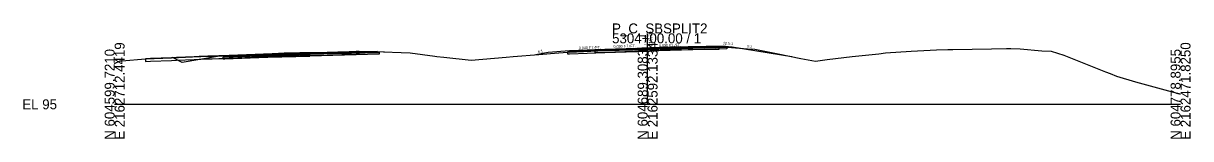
# Model space of a CAD drawing. Extents: x -26 to 1303, y -10 to 12033.
# Drawn here: x 974.3 to 1302.8, y -9.7 to 22.8 of the extents above; entities that cross this region are included whole.
import ezdxf

# ---------------------------------------------------------------- set-up
doc = ezdxf.new("R2010")
doc.units = 0
for name, color, linetype in [('RD_GPK_XS_Cell', 7, 'Continuous'), ('RD_XS_Base', 7, 'Continuous'), ('RD_XS_ExGround', 7, 'Continuous'), ('RD_XS_ExPaveRet', 7, 'Continuous'), ('RD_XS_Greenside', 7, 'Continuous'), ('RD_XS_Pave', 7, 'Continuous'), ('RD_XS_PaveOvlay_CP', 7, 'Continuous'), ('RD_XS_TieSlope', 7, 'Continuous'), ('RD_XS_TX_Elev_EX', 7, 'Continuous'), ('RD_XS_TX_Elev_PR', 7, 'Continuous'), ('RD_XS_TX_ShdSlope', 7, 'Continuous'), ('RD_XS_TX_Slope', 7, 'Continuous')]:
    doc.layers.add(name, color=color, linetype=linetype)

msp = doc.modelspace()

# ---------------------------------------------------------------- linework, layer by layer
at = {"layer": 'RD_GPK_XS_Cell'}
for p, q in [((1150, 0), (1150, 20)), ((1000, 0), (1150, 0)), ((1150, 0), (1300, 0))]:
    msp.add_line(p, q, dxfattribs=at)
at = {"layer": 'RD_XS_Base'}
for p, q in [((1030.97, 13.33), (1030.47, 13.31)), ((1030.47, 13.31), (1030.47, 13.31)), ((1030.47, 13.31), (1030.47, 12.81)), ((1031.04, 13.33), (1030.97, 13.33)), ((1042.97, 13.81), (1031.04, 13.33)), ((1031.04, 12.83), (1042.97, 13.31)), ((1043.1, 13.81), (1042.97, 13.81)), ((1042.97, 13.31), (1043.1, 13.31)), ((1054.97, 14.12), (1043.1, 13.81)), ((1043.1, 13.31), (1054.97, 13.62)), ((1054.97, 14.12), (1074.47, 14.62)), ((1054.97, 13.62), (1054.97, 14.28)), ((1054.97, 14.28), (1054.97, 14.28)), ((1054.97, 14.28), (1054.97, 14.28)), ((1054.97, 14.28), (1054.97, 14.12)), ((1074.47, 14.12), (1054.97, 13.62)), ((1054.97, 14.12), (1054.97, 14.12)), ((1054.97, 13.62), (1054.97, 14.12)), ((1054.97, 14.12), (1054.97, 14.12)), ((1054.97, 14.12), (1054.97, 14.12)), ((1054.97, 13.62), (1054.97, 13.62)), ((1073.97, 14.61), (1073.97, 14.61)), ((1074.47, 14.62), (1074.47, 14.12)), ((1074.47, 14.59), (1074.47, 14.59)), ((1128, 14.74), (1127.5, 14.72)), ((1127.5, 14.72), (1127.5, 14.72)), ((1127.5, 14.72), (1127.5, 14.22)), ((1127.5, 14.22), (1128, 14.24)), ((1138, 15.14), (1128, 14.74)), ((1128, 14.74), (1128, 14.74)), ((1128, 14.24), (1138, 14.64)), ((1128, 14.24), (1128, 14.24)), ((1150, 15.47), (1138, 15.14)), ((1138, 15.14), (1138, 15.14)), ((1138, 14.64), (1150, 14.97)), ((1138, 14.64), (1138, 14.64)), ((1150, 15.47), (1171.79, 16.08)), ((1150, 14.97), (1150, 15.63)), ((1150, 15.63), (1150, 15.63)), ((1150, 15.63), (1150, 15.63)), ((1150, 15.63), (1150, 15.47)), ((1172.29, 15.6), (1150, 14.97)), ((1150, 15.47), (1150, 15.47)), ((1150, 14.97), (1150, 15.47)), ((1150, 15.47), (1150, 15.47)), ((1150, 15.47), (1150, 15.47)), ((1150, 14.97), (1150, 14.97)), ((1162, 15.81), (1162, 15.81)), ((1162, 15.81), (1162, 15.81)), ((1162, 15.31), (1162, 15.31)), ((1162, 15.31), (1162, 15.31)), ((1171.79, 16.08), (1171.79, 16.08)), ((1172.29, 16.1), (1172.29, 15.6)), ((1172.29, 16.06), (1172.29, 16.06)), ((1030.47, 12.81), (1030.97, 12.83)), ((1030.47, 12.81), (1030.47, 12.81)), ((1030.47, 12.81), (1030.47, 12.81)), ((1030.97, 12.83), (1031.04, 12.83))]:
    msp.add_line(p, q, dxfattribs=at)
at = {"layer": 'RD_XS_ExGround'}
msp.add_lwpolyline([(1000, 11.48), (1001.53, 12.23), (1001.99, 12.23), (1008.73, 12.85), (1015.97, 13.15), (1023.91, 13.48), (1024.23, 13.5), (1024.28, 13.5), (1028.18, 13.59), (1030.24, 13.67), (1034.66, 13.85), (1046.14, 14.36), (1049.24, 14.41), (1051.95, 14.46), (1053.23, 14.53), (1053.31, 14.53), (1054.68, 14.5), (1054.89, 14.5), (1064.52, 14.77), (1068.78, 14.9), (1071.33, 14.89), (1075.69, 14.78), (1080.66, 14.64), (1083.18, 14.53), (1090.16, 13.58), (1090.71, 13.5), (1092.65, 13.29), (1100.38, 12.45), (1110.16, 13.34), (1112.17, 13.5), (1119.36, 14.06), (1124.88, 14.5), (1124.99, 14.5), (1135.02, 15.3), (1135.19, 15.32), (1135.28, 15.32), (1146.34, 15.69), (1148.42, 15.79), (1150.59, 15.9), (1156.31, 16.11), (1166.5, 16.28), (1170.15, 16.28), (1172.5, 16.08), (1178.1, 15.67), (1180.14, 15.51), (1183, 15), (1186.73, 14.25), (1193.13, 12.91), (1197.3, 12.18), (1200.58, 12.6), (1207.59, 13.5), (1215.08, 14.28), (1216.98, 14.49), (1224.18, 14.94), (1231.33, 15.38), (1234.46, 15.46), (1234.73, 15.47), (1235.93, 15.49), (1246.83, 15.69), (1251.05, 15.75), (1252.26, 15.73), (1254.86, 15.67), (1260.98, 15.11), (1263.56, 14.96), (1267.1, 13.83), (1278.92, 9.17), (1280.16, 8.65), (1281.97, 7.97), (1287.32, 6.32), (1297.62, 3.56), (1300, 2.93)], dxfattribs=at)
at = {"layer": 'RD_XS_ExPaveRet'}
for points in [[(1068.78, 14.9), (1068.78, 14.9), (1068.54, 14.9), (1067.96, 14.88), (1063.93, 14.75), (1062.81, 14.73), (1056.82, 14.56), (1055.02, 14.52), (1054.15, 14.51), (1053.39, 14.53), (1053.32, 14.53), (1053.23, 14.53), (1053.2, 14.53), (1053.19, 14.53), (1052.4, 14.49), (1052.1, 14.47), (1051.6, 14.46), (1047.74, 14.39), (1046.74, 14.37), (1046.14, 14.36), (1044.37, 14.28), (1034.66, 13.85), (1032.19, 13.75), (1030.24, 13.67), (1029.34, 13.64), (1027.42, 13.59), (1026.26, 13.54), (1024.23, 13.48), (1023.94, 13.48), (1023.76, 13.48), (1022.39, 13.42), (1017.39, 13.21), (1015.97, 13.15), (1010.05, 12.9), (1008.73, 12.85), (1008.73, 12.85), (1008.73, 12.85), (1008.73, 12.63), (1008.73, 12.1), (1008.73, 12.1), (1008.73, 12.1), (1010.05, 12.15), (1015.97, 12.4), (1017.39, 12.46), (1022.39, 12.67), (1023.76, 12.73), (1023.94, 12.73), (1024.23, 12.73), (1026.26, 12.79), (1027.42, 12.84), (1029.34, 12.89), (1030.24, 12.92), (1032.19, 13), (1034.66, 13.1), (1044.37, 13.53), (1046.14, 13.61), (1046.74, 13.62), (1047.74, 13.64), (1051.6, 13.71), (1052.1, 13.72), (1052.4, 13.74), (1053.19, 13.78), (1053.2, 13.78), (1053.23, 13.78), (1053.32, 13.78), (1053.39, 13.78), (1054.15, 13.76), (1055.02, 13.77), (1056.82, 13.81), (1062.81, 13.98), (1063.93, 14), (1067.96, 14.13), (1068.54, 14.15), (1068.78, 14.15), (1068.78, 14.15), (1068.78, 14.15), (1068.78, 14.72), (1068.78, 14.9), (1068.78, 14.9)], [(1068.78, 14.9), (1068.78, 14.9), (1068.54, 14.9), (1067.96, 14.88), (1063.93, 14.75), (1062.81, 14.73), (1056.82, 14.56), (1055.02, 14.52), (1054.15, 14.51), (1053.39, 14.53), (1053.32, 14.53), (1053.23, 14.53), (1053.2, 14.53), (1053.19, 14.53), (1052.4, 14.49), (1052.1, 14.47), (1051.6, 14.46), (1047.74, 14.39), (1046.74, 14.37), (1046.14, 14.36), (1044.37, 14.28), (1034.66, 13.85), (1032.19, 13.75), (1030.24, 13.67), (1029.34, 13.64), (1027.42, 13.59), (1026.26, 13.54), (1024.23, 13.48), (1023.94, 13.48), (1023.76, 13.48), (1022.39, 13.42), (1017.39, 13.21), (1015.97, 13.15), (1010.05, 12.9), (1008.73, 12.85), (1008.73, 12.63), (1008.73, 12.1), (1010.05, 12.15), (1015.97, 12.4), (1017.39, 12.46), (1022.39, 12.67), (1023.76, 12.73), (1023.94, 12.73), (1024.23, 12.73), (1026.26, 12.79), (1027.42, 12.84), (1029.34, 12.89), (1030.24, 12.92), (1032.19, 13), (1034.66, 13.1), (1044.37, 13.53), (1046.14, 13.61), (1046.74, 13.62), (1047.74, 13.64), (1051.6, 13.71), (1052.1, 13.72), (1052.4, 13.74), (1053.19, 13.78), (1053.2, 13.78), (1053.23, 13.78), (1053.32, 13.78), (1053.39, 13.78), (1054.15, 13.76), (1055.02, 13.77), (1056.82, 13.81), (1062.81, 13.98), (1063.93, 14), (1067.96, 14.13), (1068.54, 14.15), (1068.78, 14.15), (1068.78, 14.15), (1068.78, 14.72), (1068.78, 14.9)], [(1166.5, 16.28), (1156.31, 16.11), (1156.31, 16.11), (1156.31, 16.11), (1150.59, 15.9), (1148.42, 15.79), (1148.42, 15.79), (1146.34, 15.69), (1146.34, 15.69), (1146.34, 15.69), (1135.28, 15.32), (1135.28, 15.32), (1135.19, 15.32), (1135.19, 15.32), (1135.19, 14.57), (1135.28, 14.57), (1135.28, 14.57), (1146.34, 14.94), (1146.34, 14.94), (1146.34, 14.94), (1148.42, 15.04), (1148.42, 15.04), (1150.59, 15.15), (1156.31, 15.36), (1156.31, 15.36), (1156.31, 15.36), (1166.5, 15.53), (1166.5, 15.53), (1170.15, 15.53), (1170.15, 16.28), (1170.15, 16.28), (1166.5, 16.28), (1166.5, 16.28)], [(1166.5, 16.28), (1156.31, 16.11), (1150.59, 15.9), (1148.42, 15.79), (1146.34, 15.69), (1135.28, 15.32), (1135.19, 15.32), (1135.19, 14.57), (1135.28, 14.57), (1146.34, 14.94), (1148.42, 15.04), (1150.59, 15.15), (1156.31, 15.36), (1166.5, 15.53), (1170.15, 15.53), (1170.15, 16.28), (1166.5, 16.28)]]:
    msp.add_lwpolyline(points, dxfattribs=at)
at = {"layer": 'RD_XS_Greenside'}
for p, q in [((1018.97, 11.82), (1016.27, 13.17)), ((1028.97, 13.48), (1018.97, 11.82)), ((1122, 14.58), (1118.52, 13.99)), ((1173.79, 16.24), (1190.59, 13.44))]:
    msp.add_line(p, q, dxfattribs=at)
at = {"layer": 'RD_XS_Pave'}
for p, q in [((1031.04, 13.65), (1030.97, 13.64)), ((1030.97, 13.64), (1030.97, 13.49)), ((1030.97, 13.49), (1030.97, 13.48)), ((1030.97, 13.48), (1031.04, 13.49)), ((1031.04, 13.49), (1030.97, 13.48)), ((1030.97, 13.48), (1030.97, 13.33)), ((1030.97, 13.33), (1030.97, 13.33)), ((1030.97, 13.33), (1031.04, 13.33)), ((1042.97, 14.12), (1031.04, 13.65)), ((1031.04, 13.49), (1042.97, 13.96)), ((1042.97, 13.96), (1031.04, 13.49)), ((1031.04, 13.33), (1042.97, 13.81)), ((1043.1, 14.13), (1042.97, 14.12)), ((1042.97, 13.96), (1043.1, 13.97)), ((1043.1, 13.97), (1042.97, 13.96)), ((1042.97, 13.81), (1043.1, 13.81)), ((1054.97, 14.44), (1043.1, 14.13)), ((1043.1, 13.97), (1054.97, 14.28)), ((1054.97, 14.28), (1043.1, 13.97)), ((1043.1, 13.81), (1054.97, 14.12)), ((1073.97, 14.93), (1054.97, 14.44)), ((1073.97, 14.77), (1054.97, 14.28)), ((1054.97, 14.28), (1073.97, 14.77)), ((1054.97, 14.12), (1073.97, 14.61)), ((1054.97, 14.44), (1054.97, 14.44)), ((1054.97, 14.28), (1054.97, 14.28)), ((1054.97, 14.28), (1054.97, 14.28)), ((1054.97, 14.28), (1054.97, 14.12)), ((1054.97, 14.28), (1054.97, 14.28)), ((1054.97, 14.12), (1054.97, 14.28)), ((1054.97, 14.28), (1054.97, 14.28)), ((1054.97, 14.28), (1054.97, 14.28)), ((1054.97, 14.12), (1054.97, 14.12)), ((1054.97, 14.12), (1054.97, 14.12)), ((1073.97, 14.77), (1073.97, 14.93)), ((1073.97, 14.93), (1073.97, 14.93)), ((1073.97, 14.61), (1073.97, 14.77)), ((1073.97, 14.77), (1073.97, 14.77)), ((1138, 15.46), (1128, 15.06)), ((1128, 14.9), (1138, 15.3)), ((1138, 15.3), (1128, 14.9)), ((1128, 14.74), (1138, 15.14)), ((1128, 15.06), (1128, 15.06)), ((1128, 15.06), (1128, 14.9)), ((1128, 14.9), (1128, 14.9)), ((1128, 14.9), (1128, 14.74)), ((1150, 15.79), (1138, 15.46)), ((1138, 15.3), (1150, 15.63)), ((1150, 15.63), (1138, 15.3)), ((1138, 15.14), (1150, 15.47)), ((1138, 15.46), (1138, 15.46)), ((1138, 15.3), (1138, 15.3)), ((1138, 15.3), (1138, 15.3)), ((1138, 15.14), (1138, 15.14)), ((1171.79, 16.4), (1150, 15.79)), ((1171.79, 16.24), (1150, 15.63)), ((1150, 15.63), (1171.79, 16.24)), ((1150, 15.47), (1172.29, 16.1)), ((1150, 15.79), (1150, 15.79)), ((1150, 15.63), (1150, 15.63)), ((1150, 15.63), (1150, 15.63)), ((1150, 15.63), (1150, 15.47)), ((1150, 15.63), (1150, 15.63)), ((1150, 15.47), (1150, 15.63)), ((1150, 15.63), (1150, 15.63)), ((1150, 15.63), (1150, 15.63)), ((1150, 15.47), (1150, 15.47)), ((1150, 15.47), (1150, 15.47)), ((1162, 16.13), (1162, 16.13)), ((1162, 16.13), (1162, 16.13)), ((1162, 15.97), (1162, 15.97)), ((1162, 15.97), (1162, 15.97)), ((1162, 15.97), (1162, 15.97)), ((1162, 15.97), (1162, 15.97)), ((1162, 15.81), (1162, 15.81)), ((1162, 15.81), (1162, 15.81)), ((1171.79, 16.24), (1171.79, 16.4)), ((1171.79, 16.4), (1171.79, 16.4)), ((1171.79, 16.08), (1171.79, 16.24)), ((1171.79, 16.24), (1171.79, 16.24))]:
    msp.add_line(p, q, dxfattribs=at)
at = {"layer": 'RD_XS_PaveOvlay_CP'}
for p, q in [((1031.04, 13.65), (1030.97, 13.64)), ((1042.97, 14.12), (1031.04, 13.65)), ((1043.1, 14.13), (1042.97, 14.12)), ((1054.97, 14.44), (1043.1, 14.13)), ((1073.97, 14.93), (1054.97, 14.44)), ((1054.97, 14.44), (1054.97, 14.44)), ((1138, 15.46), (1128, 15.06)), ((1150, 15.79), (1138, 15.46)), ((1138, 15.46), (1138, 15.46)), ((1171.79, 16.4), (1150, 15.79)), ((1150, 15.79), (1150, 15.79)), ((1162, 16.13), (1162, 16.13)), ((1162, 16.13), (1162, 16.13))]:
    msp.add_line(p, q, dxfattribs=at)
at = {"layer": 'RD_XS_TieSlope'}
for p, q in [((1030.97, 13.64), (1028.97, 13.48)), ((1073.97, 14.93), (1075.91, 14.77)), ((1128, 15.06), (1122, 14.58)), ((1171.79, 16.4), (1173.79, 16.24))]:
    msp.add_line(p, q, dxfattribs=at)

# ---------------------------------------------------------------- texts
at = {"layer": 'RD_GPK_XS_Cell'}
for s, p in [('5304+00.00 / 1', (1140, 17.2)), ('P_C_SBSPLIT2', (1140, 20)), ('EL 95', (974, -1.4))]:
    msp.add_text(s, height=2.8, dxfattribs=at).set_placement(p)
for s, p in [('E 2162712.4419', (1002.8, -10)), ('E 2162592.1334', (1152.8, -10)), ('E 2162471.8250', (1302.8, -10)), ('N 604599.7210', (1000, -10)), ('N 604689.3083', (1150, -10)), ('N 604778.8955', (1300, -10))]:
    msp.add_text(s, height=2.8, rotation=90, dxfattribs=at).set_placement(p)
at = {"layer": 'RD_XS_TX_Elev_EX'}
msp.add_text('110.87', height=0.6, rotation=90, dxfattribs=at).set_placement((1149.67, 16.73))
at = {"layer": 'RD_XS_TX_Elev_PR'}
msp.add_text('110.79', height=1, rotation=90, dxfattribs=at).set_placement((1151.3, 16.31))
at = {"layer": 'RD_XS_TX_ShdSlope'}
msp.add_text('12.5:1', height=0.75, rotation=355.4261, dxfattribs=at).set_placement((1171.18, 16.91))
at = {"layer": 'RD_XS_TX_Slope'}
for s, rotation, p in [('0.040 FT./FT.', 2.2906, (1130.62, 15.49)), ('0.030 FT./FT.', 1.7184, (1140.41, 15.91)), ('0.030 FT./FT.', 1.7184, (1153.16, 16.18)), ('6:1', 350.5358, (1177.92, 16.05)), ('6:1', 9.4623, (1119.17, 14.47))]:
    msp.add_text(s, height=0.75, rotation=rotation, dxfattribs=at).set_placement(p)

doc.saveas('drawing.dxf')
